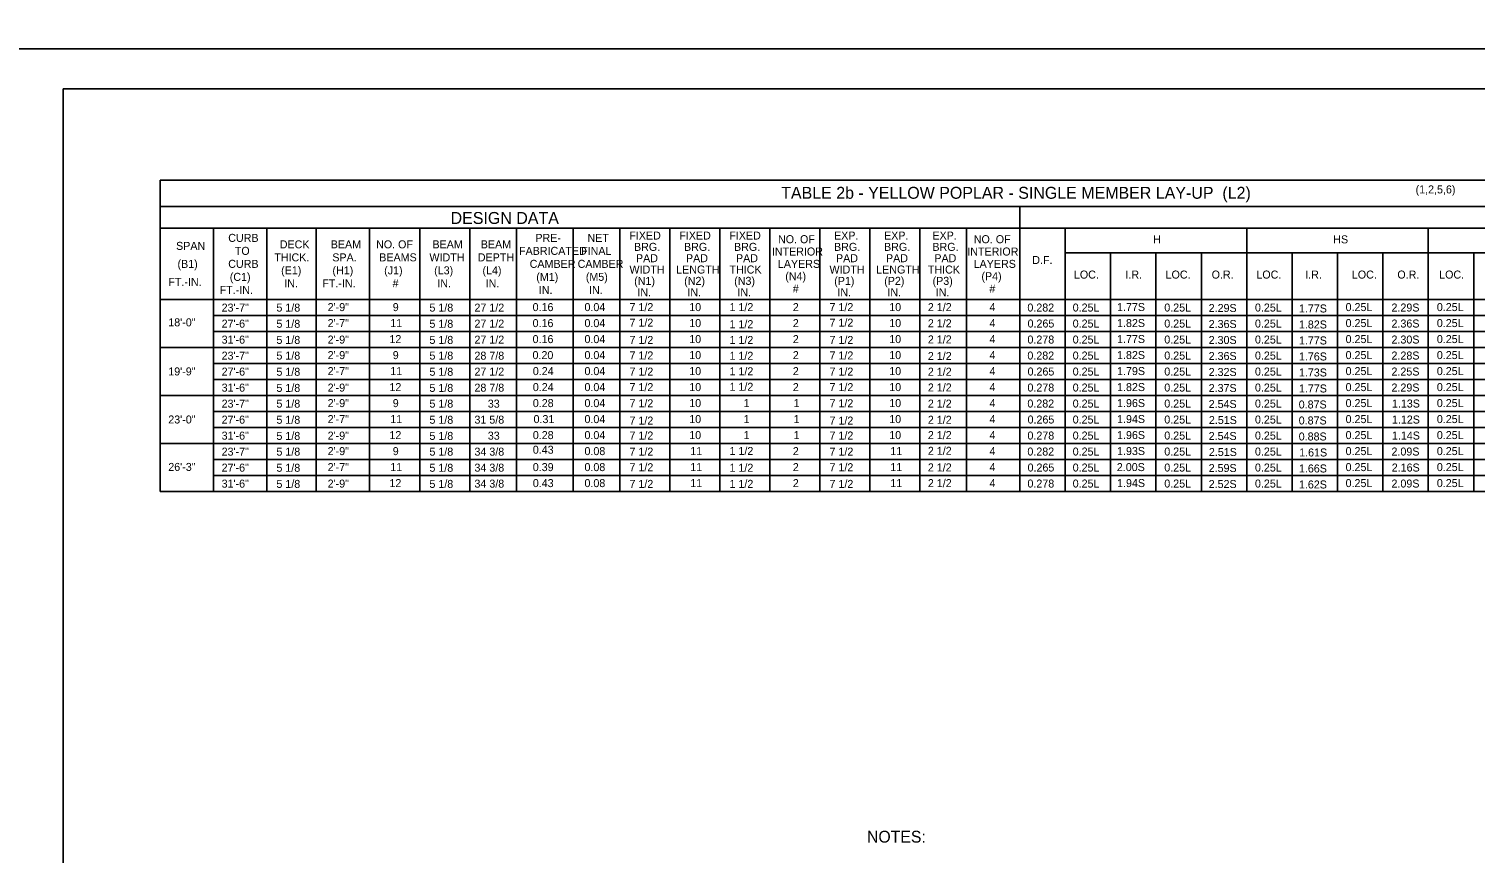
# Model space of a CAD drawing. Extents: x -5022 to -159, y 1126 to 7226.
# Drawn here: x -3813 to -3271, y 3200 to 3509 of the extents above; entities that cross this region are included whole.
import ezdxf

# ---------------------------------------------------------------- set-up
doc = ezdxf.new("R2010")
doc.units = 0
for name, color, linetype in [('2', 7, 'Continuous'), ('3', 7, 'Continuous'), ('PLT-BNDY', 7, 'Continuous')]:
    doc.layers.add(name, color=color, linetype=linetype)

msp = doc.modelspace()

# ---------------------------------------------------------------- linework, layer by layer
at = {"layer": '2'}
for p, q in [((-3014.13, 3486.81), (-3800.13, 3486.81)), ((-3800.13, 3486.81), (-3800.13, 2922.81))]:
    msp.add_line(p, q, dxfattribs=at)
at = {"layer": '3'}
for p, q in [((-3763.75, 3452.6), (-3763.75, 3335.79)), ((-3763.75, 3452.6), (-3048.9, 3452.6)), ((-3763.75, 3442.68), (-3048.9, 3442.68)), ((-3441.49, 3442.68), (-3441.49, 3335.8)), ((-3763.75, 3434.61), (-3048.9, 3434.61)), ((-3743.75, 3434.61), (-3743.75, 3335.79)), ((-3723.75, 3434.61), (-3723.75, 3335.79)), ((-3705.25, 3434.61), (-3705.25, 3335.79)), ((-3685.25, 3434.61), (-3685.25, 3335.79)), ((-3666.5, 3434.61), (-3666.5, 3335.79)), ((-3647.75, 3434.61), (-3647.75, 3335.79)), ((-3630.25, 3434.22), (-3630.25, 3335.79)), ((-3609, 3434.61), (-3609, 3335.79)), ((-3591.5, 3434.61), (-3591.5, 3335.79)), ((-3572.75, 3434.61), (-3572.75, 3335.79)), ((-3554, 3434.61), (-3554, 3335.79)), ((-3535.25, 3434.61), (-3535.25, 3335.8)), ((-3516.5, 3434.61), (-3516.5, 3335.8)), ((-3497.75, 3434.61), (-3497.75, 3335.8)), ((-3478.99, 3434.61), (-3478.99, 3335.8)), ((-3461.49, 3434.61), (-3461.49, 3335.8)), ((-3424.47, 3434.61), (-3424.47, 3335.8)), ((-3356.38, 3434.61), (-3356.38, 3335.8)), ((-3288.3, 3434.61), (-3288.3, 3335.8)), ((-3424.47, 3425.4), (-3048.9, 3425.4)), ((-3407.44, 3425.4), (-3407.44, 3335.8)), ((-3390.42, 3425.4), (-3390.42, 3335.8)), ((-3373.4, 3425.4), (-3373.4, 3335.8)), ((-3339.36, 3425.4), (-3339.36, 3335.8)), ((-3322.34, 3425.4), (-3322.34, 3335.8)), ((-3305.32, 3425.4), (-3305.32, 3335.8)), ((-3271.28, 3425.4), (-3271.28, 3335.8)), ((-3763.75, 3407.8), (-3048.9, 3407.8)), ((-3743.75, 3401.8), (-3048.9, 3401.8)), ((-3743.75, 3395.8), (-3048.9, 3395.8)), ((-3763.75, 3389.8), (-3048.9, 3389.8)), ((-3743.75, 3383.79), (-3048.9, 3383.8)), ((-3743.75, 3377.79), (-3048.9, 3377.8)), ((-3763.75, 3371.79), (-3048.9, 3371.8)), ((-3743.75, 3365.79), (-3048.9, 3365.8)), ((-3743.75, 3359.8), (-3048.9, 3359.8)), ((-3763.75, 3353.8), (-3048.9, 3353.8)), ((-3743.75, 3347.79), (-3048.9, 3347.8)), ((-3743.75, 3341.79), (-3048.9, 3341.8)), ((-3763.75, 3335.8), (-3048.9, 3335.8))]:
    msp.add_line(p, q, dxfattribs=at)
at = {"layer": 'PLT-BNDY'}
for points in [[(-3840.13, 4095.81), (-2999.13, 4095.81), (-2999.13, 3501.81), (-3840.13, 3501.81)], [(-3840.13, 3501.81), (-2999.13, 3501.81), (-2999.13, 2907.81), (-3840.13, 2907.81)]]:
    msp.add_lwpolyline(points, close=True, dxfattribs=at)

# ---------------------------------------------------------------- texts
at = {"layer": '2'}
for s, height, p in [('TABLE 2b - YELLOW POPLAR - SINGLE MEMBER LAY-UP  (L2)', 4.4793, (-3530.95, 3445.61)), ('(1,2,5,6)', 3, (-3293.07, 3447.62)), ('DESIGN DATA', 4.4793, (-3654.9, 3436.17)), ('CURB', 3, (-3738.28, 3429.45)), ('PRE-', 3, (-3623.11, 3429.45)), ('NET', 3, (-3603.58, 3429.45)), ('FIXED', 3, (-3587.9, 3430.33)), ('FIXED', 3, (-3569.15, 3430.33)), ('FIXED', 3, (-3550.4, 3430.33)), ('EXP.', 3, (-3511.13, 3430.33)), ('EXP.', 3, (-3492.38, 3430.33)), ('EXP.', 3, (-3474.25, 3430.33)), ('SPAN', 3, (-3757.83, 3426.45)), ('TO', 3, (-3735.82, 3424.58)), ('DECK', 3, (-3718.96, 3427.02)), ('BEAM', 3, (-3699.84, 3427.02)), ('NO. OF', 3, (-3682.84, 3427.02)), ('BEAM', 3, (-3661.71, 3427.02)), ('BEAM', 3, (-3643.59, 3427.02)), ('FABRICATED', 3, (-3629.25, 3424.58)), ('FINAL', 3, (-3605.96, 3424.58)), ('BRG.', 3, (-3586.13, 3426.08)), ('BRG.', 3, (-3567.38, 3426.08)), ('BRG.', 3, (-3548.63, 3426.08)), ('INTERIOR', 3, (-3534.45, 3424.33)), ('NO. OF', 3, (-3532.14, 3428.95)), ('BRG.', 3, (-3511.13, 3426.08)), ('BRG.', 3, (-3492.38, 3426.08)), ('BRG.', 3, (-3474.25, 3426.08)), ('INTERIOR', 3, (-3461.17, 3424.33)), ('NO. OF', 3, (-3458.74, 3428.95)), ('H', 3, (-3391.5, 3428.89)), ('HS', 3, (-3323.95, 3428.89)), ('(B1)', 3, (-3757.3, 3419.7)), ('CURB', 3, (-3738.28, 3419.71)), ('THICK.', 3, (-3721.01, 3422.14)), ('SPA.', 3, (-3699.26, 3422.14)), ('BEAMS', 3, (-3681.65, 3422.14)), ('WIDTH', 3, (-3662.84, 3422.14)), ('DEPTH', 3, (-3644.71, 3422.14)), ('CAMBER', 3, (-3625.25, 3419.71)), ('CAMBER', 3, (-3607.28, 3419.71)), ('PAD', 3, (-3585.4, 3421.83)), ('PAD', 3, (-3566.65, 3421.83)), ('PAD', 3, (-3547.9, 3421.83)), ('LAYERS', 3, (-3532.19, 3419.71)), ('PAD', 3, (-3510.4, 3421.83)), ('PAD', 3, (-3491.65, 3421.83)), ('PAD', 3, (-3473.52, 3421.83)), ('LAYERS', 3, (-3458.79, 3419.7)), ('D.F.', 3, (-3436.8, 3421.16)), ('(C1)', 3, (-3737.7, 3414.83)), ('(E1)', 3, (-3718.45, 3417.27)), ('(H1)', 3, (-3699.2, 3417.27)), ('(J1)', 3, (-3679.82, 3417.27)), ('(L3)', 3, (-3661.07, 3417.27)), ('(L4)', 3, (-3642.95, 3417.27)), ('(M1)', 3, (-3622.78, 3414.83)), ('(M5)', 3, (-3604.2, 3414.83)), ('WIDTH', 3, (-3587.83, 3417.58)), ('(N1)', 3, (-3586.07, 3413.33)), ('LENGTH', 3, (-3570.33, 3417.58)), ('(N2)', 3, (-3567.32, 3413.33)), ('THICK', 3, (-3550.33, 3417.58)), ('(N3)', 3, (-3548.57, 3413.33)), ('(N4)', 3, (-3529.42, 3415.08)), ('WIDTH', 3, (-3512.83, 3417.58)), ('(P1)', 3, (-3511.07, 3413.33)), ('LENGTH', 3, (-3495.33, 3417.58)), ('(P2)', 3, (-3492.32, 3413.33)), ('THICK', 3, (-3475.95, 3417.58)), ('(P3)', 3, (-3474.19, 3413.33)), ('(P4)', 3, (-3455.87, 3415.08)), ('LOC.', 3, (-3421.19, 3415.69)), ('I.R.', 3, (-3401.89, 3415.69)), ('LOC.', 3, (-3386.81, 3415.69)), ('O.R.', 3, (-3369.55, 3415.69)), ('LOC.', 3, (-3352.78, 3415.69)), ('I.R.', 3, (-3334.47, 3415.69)), ('LOC.', 3, (-3316.97, 3415.69)), ('O.R.', 3, (-3299.92, 3415.69)), ('LOC.', 3, (-3284.24, 3415.69)), ('FT.-IN.', 3, (-3760.73, 3412.95)), ('FT.-IN.', 3, (-3741.5, 3409.95)), ('IN.', 3, (-3717.26, 3412.39)), ('FT.-IN.', 3, (-3703.01, 3412.39)), ('#', 3, (-3676.67, 3412.39)), ('IN.', 3, (-3659.88, 3412.39)), ('IN.', 3, (-3641.76, 3412.39)), ('IN.', 3, (-3621.83, 3409.95)), ('IN.', 3, (-3603, 3409.95)), ('IN.', 3, (-3584.88, 3409.08)), ('IN.', 3, (-3566.13, 3409.08)), ('IN.', 3, (-3547.38, 3409.08)), ('#', 3, (-3526.58, 3410.45)), ('IN.', 3, (-3509.88, 3409.08)), ('IN.', 3, (-3491.13, 3409.08)), ('IN.', 3, (-3473, 3409.08)), ('#', 3, (-3452.87, 3410.45)), ('23\'-7"', 3, (-3740.76, 3403.3)), ('5 1/8', 3, (-3720.21, 3403.3)), ('2\'-9"', 3, (-3701.01, 3403.49)), ('9', 3, (-3676.59, 3403.49)), ('5 1/8', 3, (-3662.84, 3403.3)), ('27 1/2', 3, (-3645.96, 3403.3)), ('0.16', 3, (-3624.15, 3403.49)), ('0.04', 3, (-3604.71, 3403.49)), ('7 1/2', 3, (-3587.83, 3403.49)), ('10', 3, (-3565.44, 3403.49)), ('1 1/2', 3, (-3550.33, 3403.49)), ('2', 3, (-3526.58, 3403.49)), ('7 1/2', 3, (-3512.83, 3403.49)), ('10', 3, (-3490.44, 3403.49)), ('2 1/2', 3, (-3475.95, 3403.49)), ('4', 3, (-3452.83, 3403.49)), ('0.282', 3, (-3438.63, 3403.33)), ('0.25L', 3, (-3421.65, 3403.33)), ('1.77S', 3, (-3405.01, 3403.51)), ('0.25L', 3, (-3387.3, 3403.33)), ('2.29S', 3, (-3370.66, 3403.16)), ('0.25L', 3, (-3353.31, 3403.33)), ('1.77S', 3, (-3336.82, 3402.98)), ('0.25L', 3, (-3319.32, 3403.5)), ('2.29S', 3, (-3302.11, 3403.33)), ('0.25L', 3, (-3285.11, 3403.5)), ('18\'-0"', 3, (-3760.76, 3397.77)), ('27\'-6"', 3, (-3740.76, 3397.29)), ('5 1/8', 3, (-3720.21, 3397.24)), ('2\'-7"', 3, (-3701.01, 3397.49)), ('11', 3, (-3677.55, 3397.49)), ('5 1/8', 3, (-3662.84, 3397.24)), ('27 1/2', 3, (-3645.96, 3397.3)), ('0.16', 3, (-3624.15, 3397.49)), ('0.04', 3, (-3604.71, 3397.49)), ('7 1/2', 3, (-3587.83, 3397.66)), ('10', 3, (-3565.44, 3397.49)), ('1 1/2', 3, (-3550.33, 3397.09)), ('2', 3, (-3526.58, 3397.49)), ('7 1/2', 3, (-3512.83, 3397.66)), ('10', 3, (-3490.44, 3397.49)), ('2 1/2', 3, (-3475.95, 3397.43)), ('4', 3, (-3452.83, 3397.49)), ('0.265', 3, (-3438.57, 3397.33)), ('0.25L', 3, (-3421.65, 3397.33)), ('1.82S', 3, (-3405.01, 3397.51)), ('0.25L', 3, (-3387.3, 3397.33)), ('2.36S', 3, (-3370.66, 3397.15)), ('0.25L', 3, (-3353.31, 3397.33)), ('1.82S', 3, (-3336.82, 3396.98)), ('0.25L', 3, (-3319.32, 3397.5)), ('2.36S', 3, (-3302.11, 3397.33)), ('0.25L', 3, (-3285.11, 3397.5)), ('12', 3, (-3677.84, 3391.49)), ('27 1/2', 3, (-3645.96, 3391.3)), ('0.16', 3, (-3624.15, 3391.49)), ('0.04', 3, (-3604.71, 3391.49)), ('10', 3, (-3565.44, 3391.49)), ('2', 3, (-3526.58, 3391.49)), ('10', 3, (-3490.44, 3391.49)), ('2 1/2', 3, (-3475.95, 3391.37)), ('4', 3, (-3452.83, 3391.49)), ('1.77S', 3, (-3405.01, 3391.51)), ('0.25L', 3, (-3319.32, 3391.5)), ('0.25L', 3, (-3285.11, 3391.5)), ('31\'-6"', 3, (-3740.76, 3391.29)), ('5 1/8', 3, (-3720.21, 3391.19)), ('2\'-9"', 3, (-3701.01, 3391.31)), ('5 1/8', 3, (-3662.84, 3391.19)), ('7 1/2', 3, (-3587.83, 3391.18)), ('1 1/2', 3, (-3550.33, 3391.16)), ('7 1/2', 3, (-3512.83, 3391.18)), ('0.278', 3, (-3438.61, 3391.33)), ('0.25L', 3, (-3421.65, 3391.33)), ('0.25L', 3, (-3387.3, 3391.33)), ('2.30S', 3, (-3370.66, 3391.16)), ('0.25L', 3, (-3353.31, 3391.33)), ('1.77S', 3, (-3336.82, 3390.98)), ('2.30S', 3, (-3302.11, 3391.33)), ('23\'-7"', 3, (-3740.76, 3385.29)), ('5 1/8', 3, (-3720.21, 3385.3)), ('2\'-9"', 3, (-3701.01, 3385.49)), ('9', 3, (-3676.59, 3385.49)), ('5 1/8', 3, (-3662.84, 3385.3)), ('28 7/8', 3, (-3645.96, 3385.29)), ('0.20', 3, (-3624.19, 3385.49)), ('0.04', 3, (-3604.71, 3385.49)), ('7 1/2', 3, (-3587.83, 3385.35)), ('10', 3, (-3565.44, 3385.49)), ('1 1/2', 3, (-3550.33, 3385.23)), ('2', 3, (-3526.58, 3385.49)), ('7 1/2', 3, (-3512.83, 3385.35)), ('10', 3, (-3490.44, 3385.49)), ('2 1/2', 3, (-3475.95, 3385.16)), ('4', 3, (-3452.83, 3385.49)), ('0.282', 3, (-3438.63, 3385.33)), ('0.25L', 3, (-3421.65, 3385.33)), ('1.82S', 3, (-3405.01, 3385.51)), ('0.25L', 3, (-3387.3, 3385.33)), ('2.36S', 3, (-3370.66, 3385.16)), ('0.25L', 3, (-3353.31, 3385.33)), ('1.76S', 3, (-3336.82, 3384.98)), ('0.25L', 3, (-3319.32, 3385.5)), ('2.28S', 3, (-3302.11, 3385.33)), ('0.25L', 3, (-3285.11, 3385.5)), ('19\'-9"', 3, (-3760.76, 3379.37)), ('27\'-6"', 3, (-3740.76, 3379.3)), ('5 1/8', 3, (-3720.21, 3379.24)), ('2\'-7"', 3, (-3701.01, 3379.49)), ('11', 3, (-3677.55, 3379.49)), ('5 1/8', 3, (-3662.84, 3379.24)), ('27 1/2', 3, (-3645.96, 3379.3)), ('0.24', 3, (-3624.08, 3379.49)), ('0.04', 3, (-3604.71, 3379.49)), ('7 1/2', 3, (-3587.83, 3379.3)), ('10', 3, (-3565.44, 3379.49)), ('1 1/2', 3, (-3550.33, 3379.42)), ('2', 3, (-3526.58, 3379.49)), ('7 1/2', 3, (-3512.83, 3379.3)), ('10', 3, (-3490.44, 3379.49)), ('2 1/2', 3, (-3475.95, 3379.26)), ('4', 3, (-3452.83, 3379.49)), ('0.265', 3, (-3438.57, 3379.33)), ('0.25L', 3, (-3421.65, 3379.33)), ('1.79S', 3, (-3405.01, 3379.5)), ('0.25L', 3, (-3387.3, 3379.33)), ('2.32S', 3, (-3370.66, 3379.16)), ('0.25L', 3, (-3353.31, 3379.33)), ('1.73S', 3, (-3336.82, 3378.98)), ('0.25L', 3, (-3319.32, 3379.5)), ('2.25S', 3, (-3302.11, 3379.33)), ('0.25L', 3, (-3285.11, 3379.5)), ('31\'-6"', 3, (-3740.76, 3373.29)), ('5 1/8', 3, (-3720.21, 3373.19)), ('2\'-9"', 3, (-3701.01, 3373.31)), ('12', 3, (-3677.84, 3373.49)), ('5 1/8', 3, (-3662.84, 3373.19)), ('28 7/8', 3, (-3645.96, 3373.29)), ('0.24', 3, (-3624.08, 3373.49)), ('0.04', 3, (-3604.71, 3373.49)), ('7 1/2', 3, (-3587.83, 3373.47)), ('10', 3, (-3565.44, 3373.49)), ('1 1/2', 3, (-3550.33, 3373.61)), ('2', 3, (-3526.58, 3373.49)), ('7 1/2', 3, (-3512.83, 3373.47)), ('10', 3, (-3490.44, 3373.49)), ('2 1/2', 3, (-3475.95, 3373.36)), ('4', 3, (-3452.83, 3373.49)), ('0.278', 3, (-3438.61, 3373.33)), ('0.25L', 3, (-3421.65, 3373.33)), ('1.82S', 3, (-3405.01, 3373.5)), ('0.25L', 3, (-3387.3, 3373.33)), ('2.37S', 3, (-3370.66, 3373.15)), ('0.25L', 3, (-3353.31, 3373.33)), ('1.77S', 3, (-3336.82, 3372.98)), ('0.25L', 3, (-3319.32, 3373.5)), ('2.29S', 3, (-3302.11, 3373.33)), ('0.25L', 3, (-3285.11, 3373.5)), ('23\'-7"', 3, (-3740.76, 3367.29)), ('5 1/8', 3, (-3720.21, 3367.29)), ('2\'-9"', 3, (-3701.01, 3367.49)), ('9', 3, (-3676.59, 3367.49)), ('5 1/8', 3, (-3662.84, 3367.29)), ('33', 3, (-3640.96, 3367.29)), ('0.28', 3, (-3624.08, 3367.49)), ('0.04', 3, (-3604.71, 3367.49)), ('7 1/2', 3, (-3587.83, 3367.42)), ('10', 3, (-3565.44, 3367.49)), ('1', 3, (-3545.05, 3367.49)), ('1', 3, (-3526.3, 3367.49)), ('7 1/2', 3, (-3512.83, 3367.42)), ('10', 3, (-3490.44, 3367.49)), ('2 1/2', 3, (-3475.95, 3367.3)), ('4', 3, (-3452.83, 3367.49)), ('0.282', 3, (-3438.63, 3367.33)), ('0.25L', 3, (-3421.65, 3367.33)), ('1.96S', 3, (-3405.01, 3367.5)), ('0.25L', 3, (-3387.3, 3367.33)), ('2.54S', 3, (-3370.66, 3367.15)), ('0.25L', 3, (-3353.31, 3367.33)), ('0.87S', 3, (-3336.9, 3366.98)), ('0.25L', 3, (-3319.32, 3367.5)), ('1.13S', 3, (-3301.94, 3367.33)), ('0.25L', 3, (-3285.11, 3367.5)), ('23\'-0"', 3, (-3760.76, 3361.35)), ('27\'-6"', 3, (-3740.76, 3361.29)), ('5 1/8', 3, (-3720.21, 3361.24)), ('2\'-7"', 3, (-3701.01, 3361.49)), ('11', 3, (-3677.55, 3361.49)), ('5 1/8', 3, (-3662.84, 3361.24)), ('31 5/8', 3, (-3645.96, 3361.29)), ('0.31', 3, (-3623.8, 3361.49)), ('0.04', 3, (-3604.71, 3361.49)), ('7 1/2', 3, (-3587.83, 3360.94)), ('10', 3, (-3565.44, 3361.49)), ('1', 3, (-3545.05, 3361.49)), ('1', 3, (-3526.3, 3361.49)), ('7 1/2', 3, (-3512.83, 3360.94)), ('10', 3, (-3490.44, 3361.49)), ('2 1/2', 3, (-3475.95, 3361.24)), ('4', 3, (-3452.83, 3361.49)), ('0.265', 3, (-3438.57, 3361.33)), ('0.25L', 3, (-3421.65, 3361.33)), ('1.94S', 3, (-3405.01, 3361.51)), ('0.25L', 3, (-3387.3, 3361.33)), ('2.51S', 3, (-3370.58, 3361.15)), ('0.25L', 3, (-3353.31, 3361.33)), ('0.87S', 3, (-3336.9, 3360.98)), ('0.25L', 3, (-3319.32, 3361.5)), ('1.12S', 3, (-3301.94, 3361.33)), ('0.25L', 3, (-3285.11, 3361.5)), ('31\'-6"', 3, (-3740.76, 3355.29)), ('5 1/8', 3, (-3720.21, 3355.19)), ('2\'-9"', 3, (-3701.01, 3355.3)), ('12', 3, (-3677.84, 3355.49)), ('5 1/8', 3, (-3662.84, 3355.19)), ('33', 3, (-3640.96, 3355.29)), ('0.28', 3, (-3624.08, 3355.49)), ('0.04', 3, (-3604.71, 3355.49)), ('7 1/2', 3, (-3587.83, 3355.33)), ('10', 3, (-3565.44, 3355.49)), ('1', 3, (-3545.05, 3355.49)), ('1', 3, (-3526.3, 3355.49)), ('7 1/2', 3, (-3512.83, 3355.33)), ('10', 3, (-3490.44, 3355.49)), ('2 1/2', 3, (-3475.95, 3355.5)), ('4', 3, (-3452.83, 3355.49)), ('0.278', 3, (-3438.61, 3355.33)), ('0.25L', 3, (-3421.65, 3355.33)), ('1.96S', 3, (-3405.01, 3355.51)), ('0.25L', 3, (-3387.3, 3355.33)), ('2.54S', 3, (-3370.66, 3355.16)), ('0.25L', 3, (-3353.31, 3355.33)), ('0.88S', 3, (-3336.9, 3354.98)), ('0.25L', 3, (-3319.32, 3355.5)), ('1.14S', 3, (-3301.94, 3355.33)), ('0.25L', 3, (-3285.11, 3355.5)), ('23\'-7"', 3, (-3740.76, 3349.29)), ('5 1/8', 3, (-3720.21, 3349.29)), ('2\'-9"', 3, (-3701.01, 3349.49)), ('9', 3, (-3676.59, 3349.49)), ('5 1/8', 3, (-3662.84, 3349.29)), ('34 3/8', 3, (-3645.96, 3349.29)), ('0.43', 3, (-3624.08, 3350.01)), ('0.08', 3, (-3604.71, 3349.49)), ('7 1/2', 3, (-3587.83, 3349.28)), ('11', 3, (-3565.05, 3349.49)), ('1 1/2', 3, (-3550.33, 3349.55)), ('2', 3, (-3526.58, 3349.49)), ('7 1/2', 3, (-3512.83, 3349.28)), ('11', 3, (-3490.05, 3349.49)), ('2 1/2', 3, (-3475.95, 3349.6)), ('4', 3, (-3452.83, 3349.49)), ('0.282', 3, (-3438.63, 3349.33)), ('0.25L', 3, (-3421.65, 3349.33)), ('1.93S', 3, (-3405.01, 3349.51)), ('0.25L', 3, (-3387.3, 3349.33)), ('2.51S', 3, (-3370.58, 3349.16)), ('0.25L', 3, (-3353.31, 3349.33)), ('1.61S', 3, (-3336.73, 3348.98)), ('0.25L', 3, (-3319.32, 3349.5)), ('2.09S', 3, (-3302.11, 3349.33)), ('0.25L', 3, (-3285.11, 3349.5)), ('26\'-3"', 3, (-3760.76, 3343.56)), ('27\'-6"', 3, (-3740.76, 3343.29)), ('5 1/8', 3, (-3720.21, 3343.24)), ('2\'-7"', 3, (-3701.01, 3343.49)), ('11', 3, (-3677.55, 3343.49)), ('5 1/8', 3, (-3662.84, 3343.24)), ('34 3/8', 3, (-3645.96, 3343.29)), ('0.39', 3, (-3624.09, 3343.49)), ('0.08', 3, (-3604.71, 3343.49)), ('7 1/2', 3, (-3587.83, 3343.45)), ('11', 3, (-3565.05, 3343.49)), ('1 1/2', 3, (-3550.33, 3343.26)), ('2', 3, (-3526.58, 3343.49)), ('7 1/2', 3, (-3512.83, 3343.45)), ('11', 3, (-3490.05, 3343.49)), ('2 1/2', 3, (-3475.95, 3343.38)), ('4', 3, (-3452.83, 3343.49)), ('0.265', 3, (-3438.57, 3343.33)), ('0.25L', 3, (-3421.65, 3343.33)), ('2.00S', 3, (-3405.09, 3343.5)), ('0.25L', 3, (-3387.3, 3343.33)), ('2.59S', 3, (-3370.66, 3343.15)), ('0.25L', 3, (-3353.31, 3343.33)), ('1.66S', 3, (-3336.82, 3342.98)), ('0.25L', 3, (-3319.32, 3343.5)), ('2.16S', 3, (-3302.02, 3343.33)), ('0.25L', 3, (-3285.11, 3343.5)), ('31\'-6"', 3, (-3740.76, 3337.29)), ('5 1/8', 3, (-3720.21, 3337.19)), ('2\'-9"', 3, (-3701.01, 3337.31)), ('12', 3, (-3677.84, 3337.49)), ('5 1/8', 3, (-3662.84, 3337.19)), ('34 3/8', 3, (-3645.96, 3337.3)), ('0.43', 3, (-3624.08, 3337.49)), ('0.08', 3, (-3604.71, 3337.49)), ('7 1/2', 3, (-3587.83, 3337.19)), ('11', 3, (-3565.05, 3337.49)), ('1 1/2', 3, (-3550.33, 3337.21)), ('2', 3, (-3526.58, 3337.49)), ('7 1/2', 3, (-3512.83, 3337.19)), ('11', 3, (-3490.05, 3337.49)), ('2 1/2', 3, (-3475.95, 3337.48)), ('4', 3, (-3452.83, 3337.49)), ('0.278', 3, (-3438.61, 3337.33)), ('0.25L', 3, (-3421.65, 3337.33)), ('1.94S', 3, (-3405.01, 3337.5)), ('0.25L', 3, (-3387.3, 3337.33)), ('0.25L', 3, (-3353.31, 3337.33)), ('0.25L', 3, (-3319.32, 3337.5)), ('2.09S', 3, (-3302.11, 3337.33)), ('0.25L', 3, (-3285.11, 3337.5)), ('2.52S', 3, (-3370.66, 3337.15)), ('1.62S', 3, (-3336.82, 3336.98)), ('NOTES:', 4.429, (-3498.77, 3204.19))]:
    msp.add_text(s, height=height, dxfattribs=at).set_placement(p)

doc.saveas('drawing.dxf')
